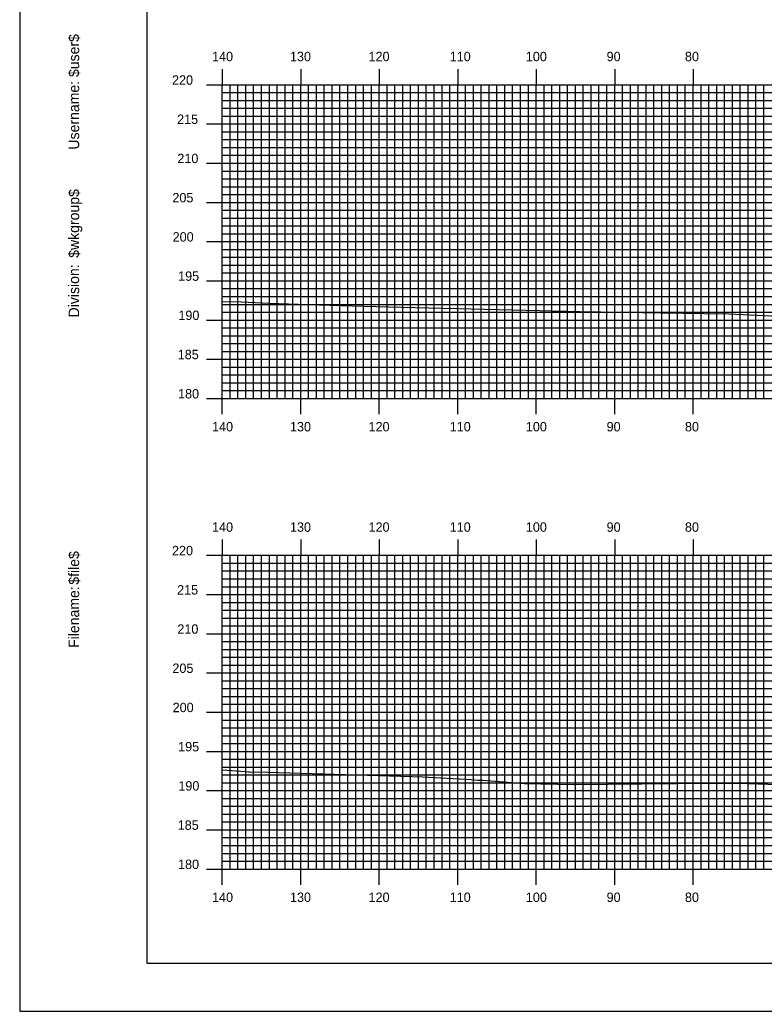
# Model space of a CAD drawing. Extents: x 1810980 to 1811323, y 442591 to 442811.
# Drawn here: x 1810980.1 to 1811074.9, y 442590.5 to 442716.9 of the extents above; entities that cross this region are included whole.
import ezdxf

# ---------------------------------------------------------------- set-up
doc = ezdxf.new("R2010")
doc.units = 0
for name, color, linetype in [('BORDER', 7, 'Continuous'), ('H_V ANNOTATION', 7, 'Continuous'), ('MAJOR', 7, 'Continuous'), ('MINOR', 7, 'Continuous'), ('PLOT BOUNDARY', 7, 'Continuous'), ('S_Roadway_Centerline', 7, 'Continuous')]:
    doc.layers.add(name, color=color, linetype=linetype)

msp = doc.modelspace()

# ---------------------------------------------------------------- linework, layer by layer
at = {"layer": 'BORDER'}
msp.add_lwpolyline([(1810996.29, 442596.67), (1811316.29, 442596.67), (1811316.29, 442806.67), (1810996.29, 442806.67)], close=True, dxfattribs=at)
at = {"layer": 'MAJOR'}
for p, q in [((1811005.89, 442710.67), (1811005.89, 442708.67)), ((1811015.89, 442710.67), (1811015.89, 442708.67)), ((1811025.89, 442710.67), (1811025.89, 442708.67)), ((1811035.89, 442710.67), (1811035.89, 442708.67)), ((1811045.89, 442710.67), (1811045.89, 442708.67)), ((1811055.89, 442710.67), (1811055.89, 442708.67)), ((1811065.89, 442710.67), (1811065.89, 442708.67)), ((1811003.89, 442708.67), (1811005.89, 442708.67)), ((1811005.89, 442708.67), (1811285.89, 442708.67)), ((1811005.89, 442668.67), (1811005.89, 442708.67)), ((1811005.89, 442668.67), (1811005.89, 442708.67)), ((1811005.89, 442708.67), (1811285.89, 442708.67)), ((1811015.89, 442668.67), (1811015.89, 442708.67)), ((1811025.89, 442668.67), (1811025.89, 442708.67)), ((1811035.89, 442668.67), (1811035.89, 442708.67)), ((1811045.89, 442668.67), (1811045.89, 442708.67)), ((1811055.89, 442668.67), (1811055.89, 442708.67)), ((1811065.89, 442668.67), (1811065.89, 442708.67)), ((1811003.89, 442703.67), (1811005.89, 442703.67)), ((1811005.89, 442703.67), (1811285.89, 442703.67)), ((1811003.89, 442698.67), (1811005.89, 442698.67)), ((1811005.89, 442698.67), (1811285.89, 442698.67)), ((1811003.89, 442693.67), (1811005.89, 442693.67)), ((1811005.89, 442693.67), (1811285.89, 442693.67)), ((1811003.89, 442688.67), (1811005.89, 442688.67)), ((1811005.89, 442688.67), (1811285.89, 442688.67)), ((1811003.89, 442683.67), (1811005.89, 442683.67)), ((1811005.89, 442683.67), (1811285.89, 442683.67)), ((1811003.89, 442678.67), (1811005.89, 442678.67)), ((1811005.89, 442678.67), (1811285.89, 442678.67)), ((1811003.89, 442673.67), (1811005.89, 442673.67)), ((1811005.89, 442673.67), (1811285.89, 442673.67)), ((1811003.89, 442668.67), (1811005.89, 442668.67)), ((1811005.89, 442668.67), (1811285.89, 442668.67)), ((1811005.89, 442668.67), (1811285.89, 442668.67)), ((1811005.89, 442666.66), (1811005.89, 442668.67)), ((1811015.89, 442666.66), (1811015.89, 442668.67)), ((1811025.89, 442666.66), (1811025.89, 442668.67)), ((1811035.89, 442666.66), (1811035.89, 442668.67)), ((1811045.89, 442666.66), (1811045.89, 442668.67)), ((1811055.89, 442666.66), (1811055.89, 442668.67)), ((1811065.89, 442666.66), (1811065.89, 442668.67)), ((1811005.89, 442650.67), (1811005.89, 442648.67)), ((1811015.89, 442650.67), (1811015.89, 442648.67)), ((1811025.89, 442650.67), (1811025.89, 442648.67)), ((1811035.89, 442650.67), (1811035.89, 442648.67)), ((1811045.89, 442650.67), (1811045.89, 442648.67)), ((1811055.89, 442650.67), (1811055.89, 442648.67)), ((1811065.89, 442650.67), (1811065.89, 442648.67)), ((1811003.89, 442648.67), (1811005.89, 442648.67)), ((1811005.89, 442648.67), (1811285.89, 442648.67)), ((1811005.89, 442608.67), (1811005.89, 442648.67)), ((1811005.89, 442608.67), (1811005.89, 442648.67)), ((1811005.89, 442648.67), (1811285.89, 442648.67)), ((1811015.89, 442608.67), (1811015.89, 442648.67)), ((1811025.89, 442608.67), (1811025.89, 442648.67)), ((1811035.89, 442608.67), (1811035.89, 442648.67)), ((1811045.89, 442608.67), (1811045.89, 442648.67)), ((1811055.89, 442608.67), (1811055.89, 442648.67)), ((1811065.89, 442608.67), (1811065.89, 442648.67)), ((1811003.89, 442643.67), (1811005.89, 442643.67)), ((1811005.89, 442643.67), (1811285.89, 442643.67)), ((1811003.89, 442638.67), (1811005.89, 442638.67)), ((1811005.89, 442638.67), (1811285.89, 442638.67)), ((1811003.89, 442633.67), (1811005.89, 442633.67)), ((1811005.89, 442633.67), (1811285.89, 442633.67)), ((1811003.89, 442628.67), (1811005.89, 442628.67)), ((1811005.89, 442628.67), (1811285.89, 442628.67)), ((1811003.89, 442623.67), (1811005.89, 442623.67)), ((1811005.89, 442623.67), (1811285.89, 442623.67)), ((1811003.89, 442618.67), (1811005.89, 442618.67)), ((1811005.89, 442618.67), (1811285.89, 442618.67)), ((1811003.89, 442613.67), (1811005.89, 442613.67)), ((1811005.89, 442613.67), (1811285.89, 442613.67)), ((1811003.89, 442608.67), (1811005.89, 442608.67)), ((1811005.89, 442608.67), (1811285.89, 442608.67)), ((1811005.89, 442608.67), (1811285.89, 442608.67)), ((1811005.89, 442606.66), (1811005.89, 442608.67)), ((1811015.89, 442606.66), (1811015.89, 442608.67)), ((1811025.89, 442606.66), (1811025.89, 442608.67)), ((1811035.89, 442606.66), (1811035.89, 442608.67)), ((1811045.89, 442606.66), (1811045.89, 442608.67)), ((1811055.89, 442606.66), (1811055.89, 442608.67)), ((1811065.89, 442606.66), (1811065.89, 442608.67))]:
    msp.add_line(p, q, dxfattribs=at)
at = {"layer": 'MINOR'}
for p, q in [((1811006.89, 442668.67), (1811006.89, 442708.67)), ((1811007.89, 442668.67), (1811007.89, 442708.67)), ((1811008.89, 442668.67), (1811008.89, 442708.67)), ((1811009.89, 442668.67), (1811009.89, 442708.67)), ((1811010.89, 442668.67), (1811010.89, 442708.67)), ((1811011.89, 442668.67), (1811011.89, 442708.67)), ((1811012.89, 442668.67), (1811012.89, 442708.67)), ((1811013.89, 442668.67), (1811013.89, 442708.67)), ((1811014.89, 442668.67), (1811014.89, 442708.67)), ((1811016.89, 442668.67), (1811016.89, 442708.67)), ((1811017.89, 442668.67), (1811017.89, 442708.67)), ((1811018.89, 442668.67), (1811018.89, 442708.67)), ((1811019.89, 442668.67), (1811019.89, 442708.67)), ((1811020.89, 442668.67), (1811020.89, 442708.67)), ((1811021.89, 442668.67), (1811021.89, 442708.67)), ((1811022.89, 442668.67), (1811022.89, 442708.67)), ((1811023.89, 442668.67), (1811023.89, 442708.67)), ((1811024.89, 442668.67), (1811024.89, 442708.67)), ((1811026.89, 442668.67), (1811026.89, 442708.67)), ((1811027.89, 442668.67), (1811027.89, 442708.67)), ((1811028.89, 442668.67), (1811028.89, 442708.67)), ((1811029.89, 442668.67), (1811029.89, 442708.67)), ((1811030.89, 442668.67), (1811030.89, 442708.67)), ((1811031.89, 442668.67), (1811031.89, 442708.67)), ((1811032.89, 442668.67), (1811032.89, 442708.67)), ((1811033.89, 442668.67), (1811033.89, 442708.67)), ((1811034.89, 442668.67), (1811034.89, 442708.67)), ((1811036.89, 442668.67), (1811036.89, 442708.67)), ((1811037.89, 442668.67), (1811037.89, 442708.67)), ((1811038.89, 442668.67), (1811038.89, 442708.67)), ((1811039.89, 442668.67), (1811039.89, 442708.67)), ((1811040.89, 442668.67), (1811040.89, 442708.67)), ((1811041.89, 442668.67), (1811041.89, 442708.67)), ((1811042.89, 442668.67), (1811042.89, 442708.67)), ((1811043.89, 442668.67), (1811043.89, 442708.67)), ((1811044.89, 442668.67), (1811044.89, 442708.67)), ((1811046.89, 442668.67), (1811046.89, 442708.67)), ((1811047.89, 442668.67), (1811047.89, 442708.67)), ((1811048.89, 442668.67), (1811048.89, 442708.67)), ((1811049.89, 442668.67), (1811049.89, 442708.67)), ((1811050.89, 442668.67), (1811050.89, 442708.67)), ((1811051.89, 442668.67), (1811051.89, 442708.67)), ((1811052.89, 442668.67), (1811052.89, 442708.67)), ((1811053.89, 442668.67), (1811053.89, 442708.67)), ((1811054.89, 442668.67), (1811054.89, 442708.67)), ((1811056.89, 442668.67), (1811056.89, 442708.67)), ((1811057.89, 442668.67), (1811057.89, 442708.67)), ((1811058.89, 442668.67), (1811058.89, 442708.67)), ((1811059.89, 442668.67), (1811059.89, 442708.67)), ((1811060.89, 442668.67), (1811060.89, 442708.67)), ((1811061.89, 442668.67), (1811061.89, 442708.67)), ((1811062.89, 442668.67), (1811062.89, 442708.67)), ((1811063.89, 442668.67), (1811063.89, 442708.67)), ((1811064.89, 442668.67), (1811064.89, 442708.67)), ((1811066.89, 442668.67), (1811066.89, 442708.67)), ((1811067.89, 442668.67), (1811067.89, 442708.67)), ((1811068.89, 442668.67), (1811068.89, 442708.67)), ((1811069.89, 442668.67), (1811069.89, 442708.67)), ((1811070.89, 442668.67), (1811070.89, 442708.67)), ((1811071.89, 442668.67), (1811071.89, 442708.67)), ((1811072.89, 442668.67), (1811072.89, 442708.67)), ((1811073.89, 442668.67), (1811073.89, 442708.67)), ((1811074.89, 442668.67), (1811074.89, 442708.67)), ((1811005.89, 442707.67), (1811285.89, 442707.67)), ((1811005.89, 442707.67), (1811007.89, 442707.67)), ((1811005.89, 442706.67), (1811285.89, 442706.67)), ((1811005.89, 442706.67), (1811007.89, 442706.67)), ((1811005.89, 442705.67), (1811285.89, 442705.67)), ((1811005.89, 442705.67), (1811007.89, 442705.67)), ((1811005.89, 442704.67), (1811285.89, 442704.67)), ((1811005.89, 442704.67), (1811007.89, 442704.67)), ((1811005.89, 442702.67), (1811285.89, 442702.67)), ((1811005.89, 442702.67), (1811007.89, 442702.67)), ((1811005.89, 442701.67), (1811285.89, 442701.67)), ((1811005.89, 442701.67), (1811007.89, 442701.67)), ((1811005.89, 442700.67), (1811285.89, 442700.67)), ((1811005.89, 442700.67), (1811007.89, 442700.67)), ((1811005.89, 442699.67), (1811285.89, 442699.67)), ((1811005.89, 442699.67), (1811007.89, 442699.67)), ((1811005.89, 442697.67), (1811285.89, 442697.67)), ((1811005.89, 442697.67), (1811007.89, 442697.67)), ((1811005.89, 442696.67), (1811285.89, 442696.67)), ((1811005.89, 442696.67), (1811007.89, 442696.67)), ((1811005.89, 442695.67), (1811285.89, 442695.67)), ((1811005.89, 442695.67), (1811007.89, 442695.67)), ((1811005.89, 442694.67), (1811285.89, 442694.67)), ((1811005.89, 442694.67), (1811007.89, 442694.67)), ((1811005.89, 442692.67), (1811285.89, 442692.67)), ((1811005.89, 442692.67), (1811007.89, 442692.67)), ((1811005.89, 442691.67), (1811285.89, 442691.67)), ((1811005.89, 442691.67), (1811007.89, 442691.67)), ((1811005.89, 442690.67), (1811285.89, 442690.67)), ((1811005.89, 442690.67), (1811007.89, 442690.67)), ((1811005.89, 442689.67), (1811285.89, 442689.67)), ((1811005.89, 442689.67), (1811007.89, 442689.67)), ((1811005.89, 442687.67), (1811285.89, 442687.67)), ((1811005.89, 442687.67), (1811007.89, 442687.67)), ((1811005.89, 442686.67), (1811285.89, 442686.67)), ((1811005.89, 442686.67), (1811007.89, 442686.67)), ((1811005.89, 442685.67), (1811285.89, 442685.67)), ((1811005.89, 442685.67), (1811007.89, 442685.67)), ((1811005.89, 442684.67), (1811285.89, 442684.67)), ((1811005.89, 442684.67), (1811007.89, 442684.67)), ((1811005.89, 442682.67), (1811285.89, 442682.67)), ((1811005.89, 442682.67), (1811007.89, 442682.67)), ((1811005.89, 442681.67), (1811285.89, 442681.67)), ((1811005.89, 442681.67), (1811007.89, 442681.67)), ((1811005.89, 442680.67), (1811285.89, 442680.67)), ((1811005.89, 442680.67), (1811007.89, 442680.67)), ((1811005.89, 442679.67), (1811285.89, 442679.67)), ((1811005.89, 442679.67), (1811007.89, 442679.67)), ((1811005.89, 442677.67), (1811285.89, 442677.67)), ((1811005.89, 442677.67), (1811007.89, 442677.67)), ((1811005.89, 442676.67), (1811285.89, 442676.67)), ((1811005.89, 442676.67), (1811007.89, 442676.67)), ((1811005.89, 442675.67), (1811285.89, 442675.67)), ((1811005.89, 442675.67), (1811007.89, 442675.67)), ((1811005.89, 442674.67), (1811285.89, 442674.67)), ((1811005.89, 442674.67), (1811007.89, 442674.67)), ((1811005.89, 442672.67), (1811285.89, 442672.67)), ((1811005.89, 442672.67), (1811007.89, 442672.67)), ((1811005.89, 442671.67), (1811285.89, 442671.67)), ((1811005.89, 442671.67), (1811007.89, 442671.67)), ((1811005.89, 442670.67), (1811285.89, 442670.67)), ((1811005.89, 442670.67), (1811007.89, 442670.67)), ((1811005.89, 442669.67), (1811285.89, 442669.67)), ((1811005.89, 442669.67), (1811007.89, 442669.67)), ((1811006.89, 442608.67), (1811006.89, 442648.67)), ((1811007.89, 442608.67), (1811007.89, 442648.67)), ((1811008.89, 442608.67), (1811008.89, 442648.67)), ((1811009.89, 442608.67), (1811009.89, 442648.67)), ((1811010.89, 442608.67), (1811010.89, 442648.67)), ((1811011.89, 442608.67), (1811011.89, 442648.67)), ((1811012.89, 442608.67), (1811012.89, 442648.67)), ((1811013.89, 442608.67), (1811013.89, 442648.67)), ((1811014.89, 442608.67), (1811014.89, 442648.67)), ((1811016.89, 442608.67), (1811016.89, 442648.67)), ((1811017.89, 442608.67), (1811017.89, 442648.67)), ((1811018.89, 442608.67), (1811018.89, 442648.67)), ((1811019.89, 442608.67), (1811019.89, 442648.67)), ((1811020.89, 442608.67), (1811020.89, 442648.67)), ((1811021.89, 442608.67), (1811021.89, 442648.67)), ((1811022.89, 442608.67), (1811022.89, 442648.67)), ((1811023.89, 442608.67), (1811023.89, 442648.67)), ((1811024.89, 442608.67), (1811024.89, 442648.67)), ((1811026.89, 442608.67), (1811026.89, 442648.67)), ((1811027.89, 442608.67), (1811027.89, 442648.67)), ((1811028.89, 442608.67), (1811028.89, 442648.67)), ((1811029.89, 442608.67), (1811029.89, 442648.67)), ((1811030.89, 442608.67), (1811030.89, 442648.67)), ((1811031.89, 442608.67), (1811031.89, 442648.67)), ((1811032.89, 442608.67), (1811032.89, 442648.67)), ((1811033.89, 442608.67), (1811033.89, 442648.67)), ((1811034.89, 442608.67), (1811034.89, 442648.67)), ((1811036.89, 442608.67), (1811036.89, 442648.67)), ((1811037.89, 442608.67), (1811037.89, 442648.67)), ((1811038.89, 442608.67), (1811038.89, 442648.67)), ((1811039.89, 442608.67), (1811039.89, 442648.67)), ((1811040.89, 442608.67), (1811040.89, 442648.67)), ((1811041.89, 442608.67), (1811041.89, 442648.67)), ((1811042.89, 442608.67), (1811042.89, 442648.67)), ((1811043.89, 442608.67), (1811043.89, 442648.67)), ((1811044.89, 442608.67), (1811044.89, 442648.67)), ((1811046.89, 442608.67), (1811046.89, 442648.67)), ((1811047.89, 442608.67), (1811047.89, 442648.67)), ((1811048.89, 442608.67), (1811048.89, 442648.67)), ((1811049.89, 442608.67), (1811049.89, 442648.67)), ((1811050.89, 442608.67), (1811050.89, 442648.67)), ((1811051.89, 442608.67), (1811051.89, 442648.67)), ((1811052.89, 442608.67), (1811052.89, 442648.67)), ((1811053.89, 442608.67), (1811053.89, 442648.67)), ((1811054.89, 442608.67), (1811054.89, 442648.67)), ((1811056.89, 442608.67), (1811056.89, 442648.67)), ((1811057.89, 442608.67), (1811057.89, 442648.67)), ((1811058.89, 442608.67), (1811058.89, 442648.67)), ((1811059.89, 442608.67), (1811059.89, 442648.67)), ((1811060.89, 442608.67), (1811060.89, 442648.67)), ((1811061.89, 442608.67), (1811061.89, 442648.67)), ((1811062.89, 442608.67), (1811062.89, 442648.67)), ((1811063.89, 442608.67), (1811063.89, 442648.67)), ((1811064.89, 442608.67), (1811064.89, 442648.67)), ((1811066.89, 442608.67), (1811066.89, 442648.67)), ((1811067.89, 442608.67), (1811067.89, 442648.67)), ((1811068.89, 442608.67), (1811068.89, 442648.67)), ((1811069.89, 442608.67), (1811069.89, 442648.67)), ((1811070.89, 442608.67), (1811070.89, 442648.67)), ((1811071.89, 442608.67), (1811071.89, 442648.67)), ((1811072.89, 442608.67), (1811072.89, 442648.67)), ((1811073.89, 442608.67), (1811073.89, 442648.67)), ((1811074.89, 442608.67), (1811074.89, 442648.67)), ((1811005.89, 442647.67), (1811285.89, 442647.67)), ((1811005.89, 442647.67), (1811007.89, 442647.67)), ((1811005.89, 442646.67), (1811285.89, 442646.67)), ((1811005.89, 442646.67), (1811007.89, 442646.67)), ((1811005.89, 442645.67), (1811285.89, 442645.67)), ((1811005.89, 442645.67), (1811007.89, 442645.67)), ((1811005.89, 442644.67), (1811285.89, 442644.67)), ((1811005.89, 442644.67), (1811007.89, 442644.67)), ((1811005.89, 442642.67), (1811285.89, 442642.67)), ((1811005.89, 442642.67), (1811007.89, 442642.67)), ((1811005.89, 442641.67), (1811285.89, 442641.67)), ((1811005.89, 442641.67), (1811007.89, 442641.67)), ((1811005.89, 442640.67), (1811285.89, 442640.67)), ((1811005.89, 442640.67), (1811007.89, 442640.67)), ((1811005.89, 442639.67), (1811285.89, 442639.67)), ((1811005.89, 442639.67), (1811007.89, 442639.67)), ((1811005.89, 442637.67), (1811285.89, 442637.67)), ((1811005.89, 442637.67), (1811007.89, 442637.67)), ((1811005.89, 442636.67), (1811285.89, 442636.67)), ((1811005.89, 442636.67), (1811007.89, 442636.67)), ((1811005.89, 442635.67), (1811285.89, 442635.67)), ((1811005.89, 442635.67), (1811007.89, 442635.67)), ((1811005.89, 442634.67), (1811285.89, 442634.67)), ((1811005.89, 442634.67), (1811007.89, 442634.67)), ((1811005.89, 442632.67), (1811285.89, 442632.67)), ((1811005.89, 442632.67), (1811007.89, 442632.67)), ((1811005.89, 442631.67), (1811285.89, 442631.67)), ((1811005.89, 442631.67), (1811007.89, 442631.67)), ((1811005.89, 442630.67), (1811285.89, 442630.67)), ((1811005.89, 442630.67), (1811007.89, 442630.67)), ((1811005.89, 442629.67), (1811285.89, 442629.67)), ((1811005.89, 442629.67), (1811007.89, 442629.67)), ((1811005.89, 442627.67), (1811285.89, 442627.67)), ((1811005.89, 442627.67), (1811007.89, 442627.67)), ((1811005.89, 442626.67), (1811285.89, 442626.67)), ((1811005.89, 442626.67), (1811007.89, 442626.67)), ((1811005.89, 442625.67), (1811285.89, 442625.67)), ((1811005.89, 442625.67), (1811007.89, 442625.67)), ((1811005.89, 442624.67), (1811285.89, 442624.67)), ((1811005.89, 442624.67), (1811007.89, 442624.67)), ((1811005.89, 442622.67), (1811285.89, 442622.67)), ((1811005.89, 442622.67), (1811007.89, 442622.67)), ((1811005.89, 442621.67), (1811285.89, 442621.67)), ((1811005.89, 442621.67), (1811007.89, 442621.67)), ((1811005.89, 442620.67), (1811285.89, 442620.67)), ((1811005.89, 442620.67), (1811007.89, 442620.67)), ((1811005.89, 442619.67), (1811285.89, 442619.67)), ((1811005.89, 442619.67), (1811007.89, 442619.67)), ((1811005.89, 442617.67), (1811285.89, 442617.67)), ((1811005.89, 442617.67), (1811007.89, 442617.67)), ((1811005.89, 442616.67), (1811285.89, 442616.67)), ((1811005.89, 442616.67), (1811007.89, 442616.67)), ((1811005.89, 442615.67), (1811285.89, 442615.67)), ((1811005.89, 442615.67), (1811007.89, 442615.67)), ((1811005.89, 442614.67), (1811285.89, 442614.67)), ((1811005.89, 442614.67), (1811007.89, 442614.67)), ((1811005.89, 442612.67), (1811285.89, 442612.67)), ((1811005.89, 442612.67), (1811007.89, 442612.67)), ((1811005.89, 442611.67), (1811285.89, 442611.67)), ((1811005.89, 442611.67), (1811007.89, 442611.67)), ((1811005.89, 442610.67), (1811285.89, 442610.67)), ((1811005.89, 442610.67), (1811007.89, 442610.67)), ((1811005.89, 442609.67), (1811285.89, 442609.67)), ((1811005.89, 442609.67), (1811007.89, 442609.67))]:
    msp.add_line(p, q, dxfattribs=at)
at = {"layer": 'PLOT BOUNDARY'}
msp.add_lwpolyline([(1810980.1, 442590.55), (1811320.1, 442590.55), (1811320.1, 442810.55), (1810980.1, 442810.55)], close=True, dxfattribs=at)
at = {"layer": 'S_Roadway_Centerline'}
for points in [[(1811005.89, 442681.02), (1811008.3, 442681), (1811011.86, 442680.83), (1811016.78, 442680.66), (1811023.86, 442680.43), (1811028.72, 442680.33), (1811046.37, 442679.87), (1811047.91, 442679.85), (1811051.5, 442679.74), (1811067.23, 442679.49), (1811070.43, 442679.47), (1811075.85, 442679.22), (1811083.08, 442679.06), (1811087.21, 442679.09), (1811103, 442678.79), (1811108.78, 442678.69), (1811118.23, 442679.17), (1811127.78, 442678.76), (1811132.28, 442678.56), (1811148.46, 442678.36), (1811153.14, 442678.31), (1811160.43, 442678.41), (1811167.63, 442678.4), (1811180.71, 442678.13)], [(1811005.89, 442621.32), (1811008.85, 442621.1), (1811009.25, 442621.07), (1811009.38, 442621.07), (1811011.7, 442621), (1811031.46, 442620.43), (1811037.59, 442620.09), (1811038.45, 442620.02), (1811039.07, 442619.99), (1811044.34, 442619.57), (1811050.78, 442619.45), (1811067.96, 442619.6), (1811071.66, 442619.61), (1811079.12, 442619.36)]]:
    msp.add_lwpolyline(points, dxfattribs=at)

# ---------------------------------------------------------------- texts
at = {"layer": 'BORDER'}
for s, p in [('$user$', (1810987.66, 442709.65)), ('Username:', (1810987.66, 442700.4)), ('$wkgroup$', (1810987.66, 442686.6)), ('Division:', (1810987.66, 442679)), ('$file$', (1810987.66, 442644.92)), ('Filename:', (1810987.66, 442636.86))]:
    msp.add_text(s, height=1.339, rotation=90, dxfattribs=at).set_placement(p)
at = {"layer": 'H_V ANNOTATION'}
for s, p in [('140', (1811004.59, 442711.67)), ('130', (1811014.52, 442711.67)), ('120', (1811024.53, 442711.67)), ('110', (1811034.87, 442711.67)), ('100', (1811044.57, 442711.67)), ('90', (1811054.86, 442711.67)), ('80', (1811064.84, 442711.67)), ('220', (1810999.49, 442708.67)), ('215', (1811000.14, 442703.67)), ('210', (1811000.17, 442698.67)), ('205', (1810999.54, 442693.67)), ('200', (1810999.57, 442688.67)), ('195', (1811000.27, 442683.67)), ('190', (1811000.3, 442678.67)), ('185', (1811000.22, 442673.67)), ('180', (1811000.26, 442668.67)), ('140', (1811004.59, 442664.47)), ('130', (1811014.52, 442664.47)), ('120', (1811024.53, 442664.47)), ('110', (1811034.87, 442664.47)), ('100', (1811044.57, 442664.47)), ('90', (1811054.86, 442664.47)), ('80', (1811064.84, 442664.47)), ('140', (1811004.59, 442651.67)), ('130', (1811014.52, 442651.67)), ('120', (1811024.53, 442651.67)), ('110', (1811034.87, 442651.67)), ('100', (1811044.57, 442651.67)), ('90', (1811054.86, 442651.67)), ('80', (1811064.84, 442651.67)), ('220', (1810999.49, 442648.67)), ('215', (1811000.14, 442643.67)), ('210', (1811000.17, 442638.67)), ('205', (1810999.54, 442633.67)), ('200', (1810999.57, 442628.67)), ('195', (1811000.27, 442623.67)), ('190', (1811000.3, 442618.67)), ('185', (1811000.22, 442613.67)), ('180', (1811000.26, 442608.67)), ('140', (1811004.59, 442604.47)), ('130', (1811014.52, 442604.47)), ('120', (1811024.53, 442604.47)), ('110', (1811034.87, 442604.47)), ('100', (1811044.57, 442604.47)), ('90', (1811054.86, 442604.47)), ('80', (1811064.84, 442604.47))]:
    msp.add_text(s, height=1.2, dxfattribs=at).set_placement(p)
at = {"layer": 'MAJOR'}
for p in [(1811005.88, 442668.67), (1811005.88, 442608.67)]:
    msp.add_text('-', height=0.012, dxfattribs=at).set_placement(p)

doc.saveas('drawing.dxf')
